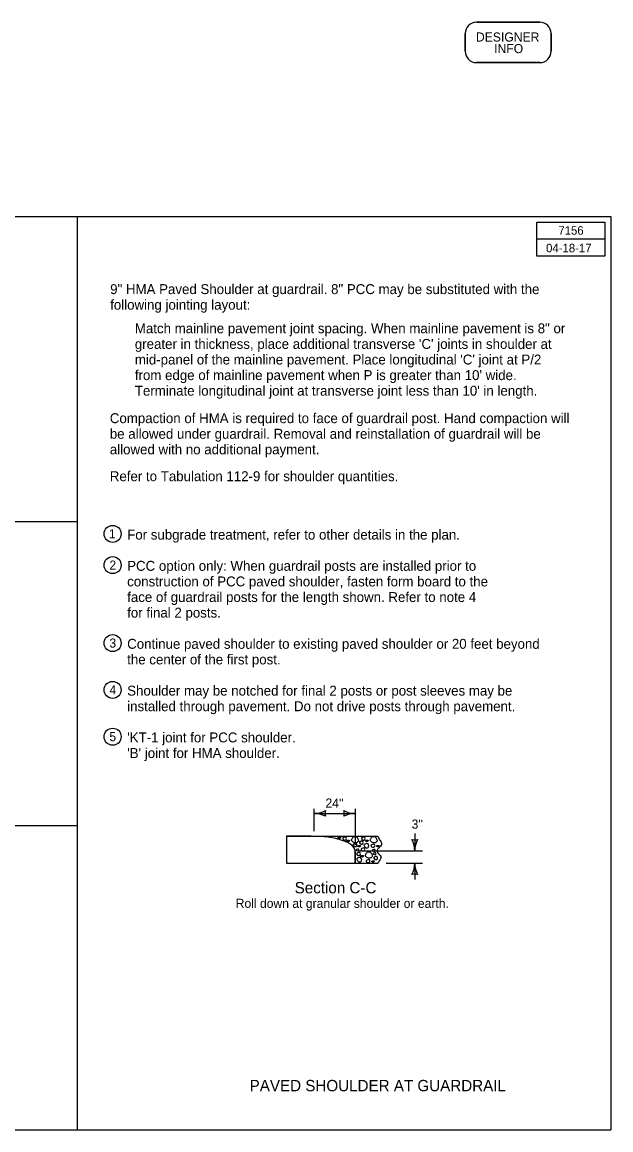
# Model space of a CAD drawing. Extents: x -1548 to 1548, y -960 to 993.
# Drawn here: x 510 to 1548, y -960 to 993 of the extents above; entities that cross this region are included whole.
import ezdxf

# ---------------------------------------------------------------- set-up
doc = ezdxf.new("R2010")
doc.units = 0
for name, color, linetype in [('dsnStdBorder', 7, 'Continuous'), ('dsnStdCells', 7, 'Continuous'), ('dsnStdDimension', 7, 'Continuous'), ('dsnStdLabel', 7, 'Continuous'), ('dsnStdLineWork', 7, 'Continuous'), ('dsnStdNameDate', 7, 'Continuous'), ('dsnStdNote', 7, 'Continuous'), ('dsnStdPattern', 7, 'Continuous'), ('dsnStdShading', 7, 'Continuous'), ('Level 4', 7, 'Continuous')]:
    doc.layers.add(name, color=color, linetype=linetype)

msp = doc.modelspace()

# ---------------------------------------------------------------- linework, layer by layer
at = {"layer": 'dsnStdBorder'}
for p, q in [((-1547.8, 650), (1547.8, 650)), ((1547.8, 650), (1547.8, -960)), ((-1547.8, -960), (1547.8, -960))]:
    msp.add_line(p, q, dxfattribs=at)
at = {"layer": 'dsnStdCells'}
for points in [[(1311.1, 992.7), (1422.5, 992.7)], [(1422.5, 992.7), (1311.1, 992.7)], [(1291.1, 941.3), (1291.1, 972.7)], [(1291.1, 972.7), (1291.1, 941.3)], [(1442.5, 972.7), (1442.5, 941.3)], [(1442.5, 941.3), (1442.5, 972.7)], [(1422.5, 921.3), (1311.1, 921.3)], [(1311.1, 921.3), (1422.5, 921.3)]]:
    msp.add_lwpolyline(points, dxfattribs=at)
for centre, start, end in [((1311.1, 972.7), 90, 180), ((1311.1, 972.7), 90, 180), ((1422.5, 972.7), 0, 90), ((1422.5, 972.7), 0, 90), ((1311.1, 941.3), 180, 270), ((1311.1, 941.3), 180, 270), ((1422.5, 941.3), 270, 0), ((1422.5, 941.3), 270, 0)]:
    msp.add_arc(centre, 20, start, end, dxfattribs=at)
at = {"layer": 'dsnStdDimension'}
for p, q in [((1024.6, -433.6), (1024.6, -394.2)), ((1024.6, -402.2), (1097.1, -402.2)), ((1097.1, -394.2), (1097.1, -457.7)), ((1202.2, -437.3), (1202.2, -468.3)), ((1104, -468.3), (1216, -468.3)), ((1151.9, -490.1), (1216, -490.1)), ((1202.2, -490.1), (1202.2, -518.7))]:
    msp.add_line(p, q, dxfattribs=at)
for centre, radius, start, end in [((1024.6, -359.7), 42.5, 270, 298.0725), ((1024.6, -444.7), 42.5, 61.9275, 90), ((1060.2, -402.2), 16.4, 162.2666, 197.7334), ((1061.5, -402.2), 16.4, 342.2666, 17.7334), ((1097.1, -359.7), 42.5, 241.9275, 270), ((1097.1, -444.7), 42.5, 90, 118.0725), ((1202.2, -432.6), 16.4, 252.2666, 287.7334), ((1159.7, -468.3), 42.5, 0, 28.0725), ((1244.7, -468.3), 42.5, 151.9275, 180), ((1159.7, -490.1), 42.5, 331.9275, 360), ((1244.7, -490.1), 42.5, 180, 208.0725), ((1202.2, -525.7), 16.4, 72.2666, 107.7334)]:
    msp.add_arc(centre, radius, start, end, dxfattribs=at)
at = {"layer": 'dsnStdLineWork'}
for p, q in [((1547.8, 650), (1547.8, 650)), ((976.2, -442.1), (976.2, -490.1)), ((976.2, -442.1), (1019.3, -442.2)), ((1019.3, -442.2), (1137, -442.2)), ((1097.1, -468.3), (1097.1, -490.1)), ((976.2, -490.1), (1097.1, -490.1)), ((1097.1, -490.1), (1137, -490.1))]:
    msp.add_line(p, q, dxfattribs=at)
msp.add_lwpolyline([(1537, 640), (1537, 580), (1417.3, 580), (1417.3, 640), (1537, 640), (1537, 610), (1417.3, 610)], dxfattribs=at)
msp.add_ellipse((1019.3, -468.3), major_axis=(77.9, 0), ratio=0.335273, start_param=0, end_param=1.570796, dxfattribs=at)
msp.add_spline([(1137, -442.2), (1138.4, -445.3), (1140.3, -448.5), (1142.1, -451.5), (1143.6, -454.6), (1143.7, -456.4), (1143, -458.1), (1140.2, -461.6), (1137, -465.1), (1135.9, -466.8), (1135.6, -467.7), (1135.4, -468.6), (1135.5, -469), (1135.8, -470.2), (1136.8, -471.8), (1139.8, -475), (1142.2, -478.1), (1142.7, -479.7), (1142.6, -480.5), (1142.5, -480.9), (1142.3, -481.3), (1137, -490.1)], degree=3, dxfattribs=at)
at = {"layer": 'dsnStdNote'}
for centre in [(669.6, 90.6), (669.6, 35.6), (669.6, -101.9), (669.6, -184.4), (669.6, -266.9)]:
    msp.add_circle(centre, 15, dxfattribs=at)
at = {"layer": 'dsnStdPattern'}
for points in [[(1068.9, -446.3), (1069.8, -446.5), (1070.3, -446.5), (1072.7, -444.1), (1068.7, -443.3), (1065.2, -445.4), (1068.1, -446.2), (1068.9, -446.3)], [(1075.3, -445.9), (1075.4, -445.3), (1075.7, -445.5), (1080.3, -442.8), (1082.7, -446), (1080.6, -450), (1075.5, -448.9), (1075.3, -446.4), (1075.3, -445.9)], [(1084.5, -451.8), (1085.4, -452), (1085.9, -452), (1088.3, -449.6), (1084.3, -448.8), (1080.8, -451), (1083.7, -451.7), (1084.5, -451.8)], [(1090.2, -449.6), (1089.9, -449.1), (1090.5, -449.5), (1092.4, -443), (1100.7, -442.8), (1103.3, -450), (1103.6, -450.8), (1098.8, -454.6), (1092.1, -452.4), (1090.5, -450.1), (1090.2, -449.6)], [(1108.3, -445.9), (1108.3, -445.3), (1108.7, -445.5), (1113.2, -442.8), (1115.6, -446), (1113.5, -450), (1108.4, -448.9), (1108.2, -446.4), (1108.3, -445.9)], [(1117.5, -451.8), (1118.3, -452), (1118.9, -452), (1121.3, -449.6), (1117.2, -448.8), (1113.8, -451), (1116.6, -451.7), (1117.5, -451.8)], [(1123.1, -449.6), (1122.9, -449.1), (1123.4, -449.5), (1125.3, -443), (1133.6, -442.8), (1136.3, -450), (1136.5, -450.8), (1131.7, -454.6), (1125, -452.4), (1123.4, -450.1), (1123.1, -449.6)], [(1093.7, -457.1), (1093.8, -456.5), (1094.1, -456.7), (1098.7, -454), (1101.1, -457.2), (1098.9, -461.3), (1093.8, -460.2), (1093.7, -457.7), (1093.7, -457.1)], [(1099.1, -466.8), (1098.7, -466.3), (1099.1, -465.9), (1103.3, -464.6), (1104.7, -468.1), (1101.5, -468.9), (1099.5, -467.3), (1099.1, -466.8)], [(1103.8, -461.1), (1104.7, -461.3), (1105.2, -461.3), (1107.6, -458.9), (1103.6, -458), (1100.1, -460.2), (1103, -460.9), (1103.8, -461.1)], [(1104.7, -453), (1104.8, -452.4), (1105.1, -452.6), (1109.7, -449.9), (1112.1, -453.1), (1110, -457.2), (1104.9, -456.1), (1104.7, -453.6), (1104.7, -453)], [(1107.6, -464.8), (1107.6, -464.3), (1108, -464.4), (1112.6, -461.8), (1115, -465), (1112.8, -469), (1107.7, -467.9), (1107.6, -465.4), (1107.6, -464.8)], [(1112.8, -459), (1112.2, -457.9), (1112.4, -457.5), (1117, -454.6), (1121, -456.4), (1122.1, -461.8), (1115.9, -464.5), (1113.4, -460.2), (1112.8, -459)], [(1125, -458.4), (1125.1, -457.8), (1125.4, -458), (1130, -455.3), (1132.4, -458.5), (1130.2, -462.6), (1125.1, -461.5), (1125, -459), (1125, -458.4)], [(1127.7, -467.2), (1127.3, -466.7), (1127.7, -466.4), (1132, -465), (1133.3, -468.5), (1130.1, -469.3), (1128.1, -467.7), (1127.7, -467.2)], [(1136.8, -461.1), (1137.6, -461.3), (1138.1, -461.3), (1140.5, -458.9), (1136.5, -458), (1133, -460.2), (1135.9, -460.9), (1136.8, -461.1)], [(1100.3, -483.6), (1099.7, -482.4), (1099.9, -482), (1104.4, -479.1), (1108.4, -481), (1109.5, -486.3), (1103.3, -489), (1100.8, -484.7), (1100.3, -483.6)], [(1099.9, -473), (1099.9, -472.4), (1100.3, -472.6), (1104.8, -469.9), (1107.2, -473.1), (1105.1, -477.1), (1100, -476.1), (1099.8, -473.6), (1099.9, -473)], [(1109.1, -479), (1109.9, -479.1), (1110.4, -479.1), (1112.8, -476.7), (1108.8, -475.9), (1105.3, -478.1), (1108.2, -478.8), (1109.1, -479)], [(1114.7, -476.7), (1114.5, -476.2), (1115, -476.6), (1116.9, -470.2), (1125.2, -469.9), (1127.8, -477.1), (1128.1, -477.9), (1123.3, -481.7), (1116.6, -479.5), (1115, -477.2), (1114.7, -476.7)], [(1116.6, -485.5), (1116.6, -485), (1117, -485.1), (1121.6, -482.5), (1124, -485.7), (1121.8, -489.7), (1116.7, -488.6), (1116.6, -486.1), (1116.6, -485.5)], [(1128.3, -488.2), (1129.2, -488.4), (1129.7, -488.4), (1132.1, -486), (1128.1, -485.2), (1124.6, -487.3), (1127.5, -488), (1128.3, -488.2)], [(1129, -473.3), (1128.6, -472.8), (1129, -472.4), (1133.3, -471.1), (1134.6, -474.6), (1131.4, -475.4), (1129.4, -473.8), (1129, -473.3)], [(1130.2, -480.1), (1130.2, -479.5), (1130.6, -479.7), (1135.1, -477), (1137.5, -480.2), (1135.4, -484.3), (1130.3, -483.2), (1130.1, -480.7), (1130.2, -480.1)]]:
    msp.add_open_spline(points, degree=3, dxfattribs=at)
at = {"layer": 'dsnStdShading'}
for p, q in [((1019.3, -442.1), (976.2, -442.1)), ((976.2, -442.1), (976.2, -490.1)), ((1097.1, -490.1), (1097.1, -468.3)), ((976.2, -490.1), (1097.1, -490.1))]:
    msp.add_line(p, q, dxfattribs=at)
msp.add_lwpolyline([(1019.3, -442.2), (1019.3, -442.1)], dxfattribs=at)
msp.add_ellipse((1019.3, -468.3), major_axis=(77.9, 0), ratio=0.335273, start_param=0, end_param=1.570796, dxfattribs=at)
at = {"layer": 'Level 4'}
for p, q in [((607.7, -960), (607.7, 650)), ((607.7, 112), (-1547.8, 112)), ((607.7, -424), (-1547.8, -424))]:
    msp.add_line(p, q, dxfattribs=at)

# ---------------------------------------------------------------- texts
at = {"layer": 'dsnStdCells'}
for s, p in [('DESIGNER', (1310.1, 958.5)), ('INFO', (1342.2, 938.1))]:
    msp.add_text(s, height=16, rotation=360, dxfattribs=at).set_placement(p)
at = {"layer": 'dsnStdDimension'}
for s, p in [("24''", (1044.7, -391.9)), ("3'' ", (1196.6, -429))]:
    msp.add_text(s, height=16, dxfattribs=at).set_placement(p)
at = {"layer": 'dsnStdLabel'}
for s, height, p in [('Section C-C', 20, (990.4, -543.1)), ('Roll down at granular shoulder or earth.', 16, (886.5, -568.7)), ('PAVED SHOULDER AT GUARDRAIL', 20, (911.1, -892))]:
    msp.add_text(s, height=height, dxfattribs=at).set_placement(p)
at = {"layer": 'dsnStdNameDate'}
for s, p in [('7156', (1455.3, 618)), ('04-18-17', (1433.6, 587))]:
    msp.add_text(s, height=15, dxfattribs=at).set_placement(p)
at = {"layer": 'dsnStdNote'}
for s, height, p in [('9" HMA Paved Shoulder at guardrail. 8" PCC may be substituted with the', 17.5, (665.2, 513.3)), ('following jointing layout:', 17.5, (665.2, 485.8)), ('Match mainline pavement joint spacing. When mainline pavement is 8" or ', 17.5, (708.7, 444.2)), ("greater in thickness, place additional transverse 'C' joints in shoulder at ", 17.5, (708.7, 416.7)), ("mid-panel of the mainline pavement. Place longitudinal 'C' joint at P/2 ", 17.5, (708.7, 389.2)), ("from edge of mainline pavement when P is greater than 10' wide. ", 17.5, (708.7, 361.7)), ("Terminate longitudinal joint at transverse joint less than 10' in length.", 17.5, (708.7, 334.2)), ('Compaction of HMA is required to face of guardrail post. Hand compaction will', 17.5, (664.6, 285.8)), ('be allowed under guardrail. Removal and reinstallation of guardrail will be', 17.5, (664.6, 258.3)), ('allowed with no additional payment.', 17.5, (664.6, 230.8)), ('Refer to Tabulation 112-9 for shoulder quantities.', 17.5, (664.6, 183.5)), ('1', 16, (662.8, 82.6)), ('For subgrade treatment, refer to other details in the plan.', 17.5, (695.2, 80.5)), ('2', 16, (663.9, 27.6)), ('PCC option only: When guardrail posts are installed prior to ', 17.5, (695.2, 25.5)), ('construction of PCC paved shoulder, fasten form board to the ', 17.5, (695.2, -2)), ('face of guardrail posts for the length shown. Refer to note 4 ', 17.5, (695.2, -29.5)), ('for final 2 posts.', 17.5, (695.2, -57)), ('3', 16, (663.8, -109.9)), ('Continue paved shoulder to existing paved shoulder or 20 feet beyond', 17.5, (695.2, -112)), ('the center of the first post.', 17.5, (695.2, -139.5)), ('4', 16, (663.9, -192.4)), ('Shoulder may be notched for final 2 posts or post sleeves may be', 17.5, (695.2, -194.5)), ('installed through pavement. Do not drive posts through pavement.', 17.5, (695.2, -222)), ('5', 16, (663.8, -274.9)), ("'KT-1 joint for PCC shoulder.", 17.5, (695.2, -277)), ("'B' joint for HMA shoulder.", 17.5, (695.2, -304.5))]:
    msp.add_text(s, height=height, dxfattribs=at).set_placement(p)

doc.saveas('drawing.dxf')
